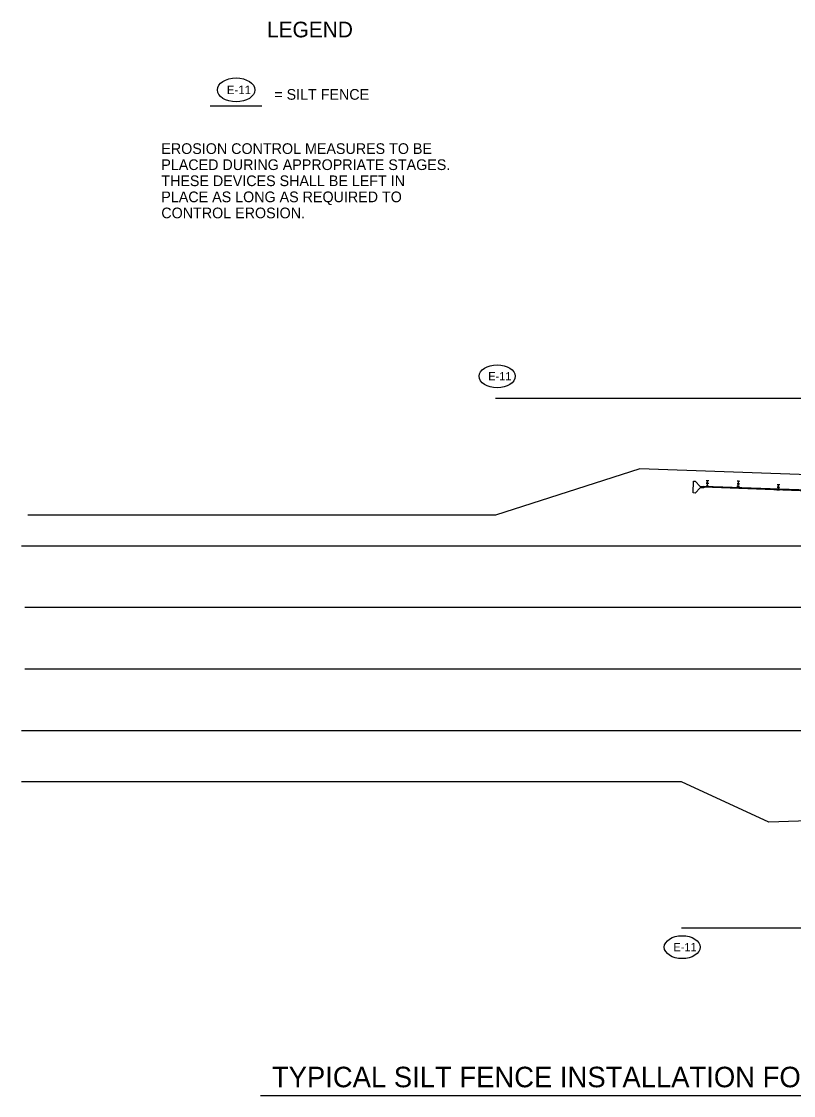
# Model space of a CAD drawing. Extents: x 1405295 to 1406670, y 2087573 to 2090763.
# Drawn here: x 1405372 to 1405824, y 2087872 to 2088500 of the extents above; entities that cross this region are included whole.
import ezdxf

# ---------------------------------------------------------------- set-up
doc = ezdxf.new("R2010")
doc.units = 0
for name, color, linetype in [('1', 7, 'Continuous'), ('22', 7, 'Continuous'), ('Default', 7, 'Continuous'), ('Level 1', 7, 'Continuous'), ('Level 44', 7, 'Continuous'), ('X_ARROWS_LEGEND', 7, 'Continuous')]:
    doc.layers.add(name, color=color, linetype=linetype)

msp = doc.modelspace()

# ---------------------------------------------------------------- linework, layer by layer
at = {"layer": '1'}
for centre in [(1405650.33, 2088292.87), (1405758.64, 2087958.85)]:
    msp.add_ellipse(centre, major_axis=(10.52, 0), ratio=0.638788, dxfattribs=at)
at = {"layer": '22'}
msp.add_line((1405511.89, 2087872.05), (1406290.43, 2087872.05), dxfattribs=at)
for points in [[(1405649.36, 2088280.09), (1406363.11, 2088280.09), (1406363.11, 2088221.33)], [(1405758.1, 2087970.09), (1406363.11, 2087970.09), (1406363.11, 2088042.57)]]:
    msp.add_lwpolyline(points, dxfattribs=at)
at = {"layer": 'Default'}
for p, q in [((1405733.89, 2088238.72), (1405649.36, 2088211.52)), ((1406213.47, 2088221.32), (1405733.89, 2088238.72)), ((1405772.62, 2088230.45), (1405773.37, 2088230.44)), ((1405772.62, 2088230.33), (1405773.37, 2088230.32)), ((1405772.68, 2088231.95), (1405773.43, 2088231.94)), ((1405773.31, 2088228.82), (1405773.37, 2088230.32)), ((1405773.37, 2088230.44), (1405773.43, 2088231.94)), ((1405773.37, 2088230.44), (1405774.12, 2088230.4)), ((1405773.37, 2088230.32), (1405774.12, 2088230.28)), ((1405773.43, 2088231.94), (1405774.18, 2088231.91)), ((1405790.71, 2088230.14), (1405791.46, 2088230.13)), ((1405790.71, 2088230.02), (1405791.46, 2088230.01)), ((1405790.77, 2088231.64), (1405791.52, 2088231.63)), ((1405791.41, 2088228.51), (1405791.46, 2088230.01)), ((1405791.46, 2088230.13), (1405791.52, 2088231.63)), ((1405791.46, 2088230.13), (1405792.21, 2088230.08)), ((1405791.46, 2088230.01), (1405792.21, 2088229.96)), ((1405791.52, 2088231.63), (1405792.27, 2088231.59)), ((1405814.16, 2088229.62), (1405814.91, 2088229.6)), ((1405814.86, 2088228.1), (1405814.91, 2088229.6)), ((1405814.91, 2088229.6), (1405815.66, 2088229.57)), ((1406213.1, 2088211.57), (1405771.29, 2088228.01)), ((1406213.14, 2088212.38), (1405771.3, 2088228.41)), ((1405772.56, 2088228.83), (1405773.31, 2088228.82)), ((1405773.31, 2088228.82), (1405774.06, 2088228.79)), ((1405790.66, 2088228.52), (1405791.41, 2088228.51)), ((1405791.41, 2088228.51), (1405792.16, 2088228.47)), ((1405814.05, 2088226.5), (1405814.8, 2088226.49)), ((1405814.11, 2088228.12), (1405814.86, 2088228.1)), ((1405814.11, 2088228), (1405814.86, 2088227.98)), ((1405814.8, 2088226.49), (1405814.86, 2088227.98)), ((1405814.8, 2088226.49), (1405815.55, 2088226.45)), ((1405814.86, 2088228.1), (1405815.61, 2088228.06)), ((1405814.86, 2088227.98), (1405815.6, 2088227.94)), ((1405649.36, 2088211.52), (1405375.78, 2088211.52)), ((1406442.16, 2088193.52), (1405372.03, 2088193.52)), ((1406442.16, 2088157.51), (1405373.91, 2088157.51)), ((1406442.16, 2088121.51), (1405373.91, 2088121.51)), ((1406444.65, 2088085.51), (1405372.03, 2088085.51))]:
    msp.add_line(p, q, dxfattribs=at)
msp.add_lwpolyline([(1405769.05, 2088228.43), (1405771.3, 2088228.41), (1405771.28, 2088227.61), (1405769.03, 2088227.62), (1405766.09, 2088224.56), (1405765.1, 2088224.58), (1405765.12, 2088231.51), (1405766.11, 2088231.49)], close=True, dxfattribs=at)
for points in [[(1405758.1, 2088055.51), (1405372.03, 2088055.51)], [(1405809.19, 2088031.96), (1405758.1, 2088055.51)], [(1406213.26, 2088045.69), (1405809.19, 2088031.96)]]:
    msp.add_lwpolyline(points, dxfattribs=at)
at = {"layer": 'Level 44'}
msp.add_lwpolyline([(1405482.45, 2088451.11), (1405512.57, 2088451.12)], dxfattribs=at)
at = {"layer": 'X_ARROWS_LEGEND'}
msp.add_ellipse((1405497.61, 2088460.4), major_axis=(10.96, 0), ratio=0.638788, dxfattribs=at)

# ---------------------------------------------------------------- texts
at = {"layer": '1'}
for p in [(1405645.13, 2088290.51), (1405753.44, 2087956.49)]:
    msp.add_text('E-11', height=4.8, rotation=359.99998, dxfattribs=at).set_placement(p)
at = {"layer": 'Default'}
msp.add_text('TYPICAL SILT FENCE INSTALLATION FOR WIDENING FOR GUARDRAIL AT BRIDGE ENDS', height=12, rotation=359.99992, dxfattribs=at).set_placement((1405518.54, 2087876.88))
at = {"layer": 'Level 1'}
for s, p in [('= SILT FENCE', (1405519.95, 2088454.66)), ('EROSION CONTROL MEASURES TO BE', (1405453.85, 2088422.94)), ('PLACED DURING APPROPRIATE STAGES. ', (1405453.85, 2088413.53)), ('THESE DEVICES SHALL BE LEFT IN', (1405453.85, 2088404.12)), ('PLACE AS LONG AS REQUIRED TO', (1405453.85, 2088394.71)), ('CONTROL EROSION.', (1405453.85, 2088385.3))]:
    msp.add_text(s, height=6.25, rotation=0.00001, dxfattribs=at).set_placement(p)
at = {"layer": 'Level 44'}
msp.add_text('LEGEND', height=9.143, rotation=0.00001, dxfattribs=at).set_placement((1405515.67, 2088491.17))
at = {"layer": 'X_ARROWS_LEGEND'}
msp.add_text('E-11', height=4.999, dxfattribs=at).set_placement((1405492.2, 2088457.94))

doc.saveas('drawing.dxf')
